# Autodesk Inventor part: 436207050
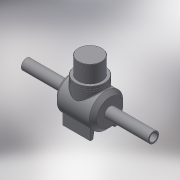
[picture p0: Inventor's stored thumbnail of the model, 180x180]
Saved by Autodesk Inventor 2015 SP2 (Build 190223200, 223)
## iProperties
Created: 2017-08
Part Number: 436207050
Material: Generic
Description: PLASSON PE BALL VALVE 50
Document SubType Name: Modeling
Designer: Кирилл
Density: 1 g/cm^3
Appearance: Default
Author: Кирилл
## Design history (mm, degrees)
derived "436207.ipt"
feature "Solid1::436207.ipt"
feature "Solid2::436207.ipt"
tag "TaggingFeature1"
body "Solid1"
other parameters: "d0" = 414, "d5" = 37.5, "d6" = 12.42, "d10" = 85, "d11" = 68, "d12" = 0.85, "d13" = 4, "d14" = 4, "d16" = 100 deg, "d17" = 48, "d18" = 9.6, "d20" = 87, "d21" = 0, "d22" = 0.85, "d26" = 6, "d28" = 0, "d29" = 1.7, "s_" = 6, "L_" = 414, "B_" = 87, "E_1" = 85
